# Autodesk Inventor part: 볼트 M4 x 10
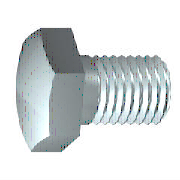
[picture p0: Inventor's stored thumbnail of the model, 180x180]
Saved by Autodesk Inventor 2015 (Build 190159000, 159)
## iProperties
Created: 2012-02
Part Number: 볼트 M4 x 10
Material: 스테인리스강
Description: 6각 머리 나사
Document SubType Name: Modeling
Standard: ISO 4017
Designer: mduedu
Standard Revision: Third edition 1999-08-15
Standards Organization: ISO
Language: ko-KR
Size Designation: M4 x 10
Categories: <MemberInstance><Categories><Category DisplayName="조임쇠" InternalName="e4da775c-781d-43d5-af7c-5136215cf5a6" Mnemonic="FSTN"><Category DisplayName="볼트" InternalN
Density: 8.08 g/cm^3
Appearance: 반광택
IsCustomPart: 0
Author: mduedu
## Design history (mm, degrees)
sketch "스케치1"
  geometry: L1 (0, 3.015)-(0, 2); L2 (2.1, 2)-(10, 2); L3 (10, 2)-(10, 0); L4 (10, 0)-(-0.4, 0); L5 (-2.48, 0)-(12.08, 0) reference; L6 (-0.4, 0)-(-0.4, 3.015); L7 (-0.4, 3.015)-(0, 3.015); L8 (2.1, 2)-(1.67, 2); L9 (1.67, 2)-(0, 2); L10 (0, -0.603)-(0, 3.618) reference
  constraints: 16 end point, 2 collinear, 2 perpendicular, 1 parallel
  dimensions: "d0" = 10 distance between parallel lines of L3 L1 (= NLG); "d1" = 7.9 distance from line of L2.start L3 (= GEL); "d2" = 4 diameter of L2 L4 (= GD); "d9" = 0.4001 distance between parallel lines of L6 L1 (computed from SD); "d10" = 6.03 diameter of L7 L4 (= SD2); "d13" = 0.42952 distance of L2.start L8.end (computed from GAL); "d14" = 4 diameter of L9 L4 (= BDM)
revolve "본체" sketch "스케치1" stored, may be unused: angle "d12" = 90 deg
sketch "스케치2"
  geometry: L1 (0, 4.041)-(3.5, 2.021); L2 (3.5, 2.021)-(3.5, -2.021); L3 (3.5, -2.021)-(0, -4.041); L4 (0, -4.041)-(-3.5, -2.021); L5 (-3.5, -2.021)-(-3.5, 2.021); L6 (-3.5, 2.021)-(0, 4.041); 2 further points
  constraints: 12 end point, 1 coincident, 1 vertical, 11 other
  dimensions: "d11" = 7 distance between parallel lines of L5 L2 (= SW)
extrude "머리" join sketch "스케치2" distance "d3" = 2.4 (= KOH - SD); taper "d4" = 0 deg
sketch "스케치4"
  geometry: L1 (-2.8, 3.5)-(-2.8, 4.041); L2 (-2.8, 4.041)-(-2.487, 4.041); L3 (-2.487, 4.041)-(-2.8, 3.5); L4 (-3.28, 0)-(0.08, 0) reference; L5 (-0.4, 4.041)-(-2.8, 4.041) reference; L6 (-2.8, 2.021)-(-2.8, 4.041) reference
  constraints: 6 end point, 2 collinear, 1 perpendicular, 1 vertical
  dimensions: "d5" = 30 deg angle of L3 L1 (= ANG1); "d19" = 7 diameter of L1.start L4 (= SW0)
revolve "모따기1" sketch "스케치4" stored, may be unused: angle "d21" = 90 deg
workplane "Work Plane1"
body "Solid1"
feature "스레드" dims "d15" = 7.9 (= GEL), "d16" = 0
chamfer "모따기2" distance "d6" = 0.42941 (= -0.5 x SPD + 0.5 x GD); stored, may be unused: second distance "d7" = 0.42952 (computed from GUL), angle "d55" = 45 deg
other parameters: "NLG" = 10 [user parameter; used in 1 equation term], "GD" = 4 (= NND) [user parameter; used in 2 equation terms], "BDM" = 4 (= NND) [user parameter; used in 1 equation term], "KOH" = 2.8 [user parameter; used in 1 equation term], "GEL" = 7.9 [user parameter; used in 2 equation terms], "SW" = 7 [user parameter; used in 2 equation terms], "SW0" = 7 (= SW) [user parameter; used in 1 equation term], "SPD" = 3.14117 (= NND - 1.2269 x PTC) [user parameter; used in 1 equation term], "SD2" = 6.03 [user parameter; used in 2 equation terms], "SD" = 0.4 [user parameter; used in 2 equation terms], "ANG1" = 30 deg [user parameter; used in 1 equation term], "GAL" = 0.42941 (= 0.61345 x PTC) [user parameter; used in 1 equation term], "GUL" = 0.42941 (= 0.61345 x PTC) [user parameter; used in 1 equation term], "d8" = 0, "RR" = 0.2 [user parameter], "d57" = 0, "d58" = 0, "TPU" = 14.28571 (computed from PTC) [user parameter], "GD1" = 3.14117 (= THREADDIA - 1.2269 x PTC) [user parameter], "THREADDIA" = 4 [user parameter; used in 1 equation term], "SDH" = 6.03 (= SD2) [user parameter], "SDHG" = 2.1 [user parameter], "TOA" = 30 deg [user parameter], "PTC" = 0.7 [user parameter; used in 5 equation terms], "NND" = 4 [user parameter; used in 3 equation terms], "E0" = 8.085 [user parameter]
